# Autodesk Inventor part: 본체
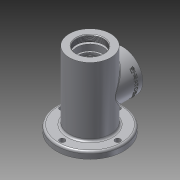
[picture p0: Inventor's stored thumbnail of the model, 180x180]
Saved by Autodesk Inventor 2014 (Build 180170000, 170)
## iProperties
Created: 2016-08
Part Number: 본체
Material: 알루미늄 6061
Document SubType Name: Modeling
Designer: 703-04
Density: 2.71 g/cm^3
Appearance: 알루미늄 - 평지
Mass: 729.842 g
Surface Area: 617.604 cm^2
Volume: 269.314 cm^3
Author: 703-04
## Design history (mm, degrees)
sketch "스케치1"
  geometry: C1 r 31 at (0, 0); 1 further point
  constraints: 1 centre point, 1 coincident
  dimensions: "d0" = 62 diameter of C1
extrude "돌출1" new body sketch "스케치1" stored distance "d1" = 102; taper "d2" = 0 deg
sketch "스케치2"
  geometry: C1 r 31 at (0, 0) reference; C2 r 50 at (0, 0)
  constraints: 1 centre point, 1 coincident
  dimensions: "d3" = 100 diameter of C2
extrude "돌출2" join sketch "스케치2" distance "d4" = 10; taper "d5" = 0 deg
sketch "스케치3"
  geometry: C1 r 50 at (0, 0) reference; C2 r 31 at (0, 0)
  constraints: 1 centre point, 1 coincident
  dimensions: "d6" = 62 diameter of C2
extrude "돌출3" join sketch "스케치3" distance "d7" = 3; taper "d8" = 0 deg
sketch "스케치4"
  geometry: L1 (31, 51)-(-31, 51) reference; L2 (0, 51)-(21, 51); L3 (21, 51)-(21, 42); L4 (21, 42)-(24, 42); L5 (24, 42)-(24, 39); L6 (24, 39)-(20, 39); L7 (20, 39)-(20, 30); L8 (20, 30)-(17.5, 30); L9 (17.5, 30)-(17.5, 26.75); L10 (17.5, 26.75)-(18.5, 26.75); L11 (18.5, 26.75)-(18.5, 25); L12 (18.5, 25)-(17.5, 25); L13 (17.5, 25)-(17.5, 14); L14 (17.5, 14)-(26, 14); L15 (26, 14)-(26, -24); L16 (26, -24)-(17.5, -24); L17 (17.5, -24)-(17.5, -35); L18 (17.5, -35)-(16.5, -35); L19 (16.5, -35)-(16.5, -40); L20 (16.5, -40)-(10, -40); L21 (10, -40)-(10, -42.7); L22 (10, -42.7)-(12.5, -42.7); L23 (12.5, -42.7)-(12.5, -49.3); L24 (12.5, -49.3)-(12.904, -50); L25 (12.904, -50)-(16.404, -50); L26 (16.404, -50)-(21, -64); L27 (-31, -64)-(31, -64) reference; L28 (21, -64)-(0, -64); L29 (0, -64)-(0, 42); L30 (21, 42)-(0, 42); L31 (0, 0)-(0, 42); L32 (0, 51)-(0, 60); 1 further point
  constraints: 60 end point, 13 parallel, 10 perpendicular, 3 point on line, 2 collinear, 2 midpoint, 2 vertical, 1 coincident
  dimensions: "d9" = 60 distance of L31.start L32.end; "d10" = 21 distance of L2.start L2.end; "d11" = 9 distance of L2.end L3.end; "d12" = 3 distance of L3.end L4.end; "d13" = 3 distance of L4.end L5.end; "d14" = 4 distance of L5.end L6.end; "d15" = 9 distance of L6.end L7.end; "d16" = 2.5 distance of L7.end L8.end; "d17" = 3.25 distance of L8.end L9.end; "d18" = 1 distance of L9.end L10.end; "d19" = 1.75 distance of L10.end L11.end; "d20" = 1 distance of L11.end L12.end; "d21" = 11 distance of L12.end L13.end; "d22" = 8.5 distance of L13.end L14.end; "d23" = 38 distance of L14.end L15.end; "d24" = 8.5 distance of L15.end L16.end; "d25" = 11 distance of L16.end L17.end; "d26" = 1 distance of L17.end L18.end; "d27" = 5 distance of L18.end L19.end; "d28" = 6.5 distance of L19.end L20.end; "d29" = 2.7 distance of L20.end L21.end; "d30" = 2.5 distance of L21.end L22.end; "d31" = 6.6 distance of L22.end L23.end; "d32" = 0.7 vertical distance of L23.end L24.end; "d33" = 30 deg angle of L23 L24; "d34" = 3.5 distance of L24.end L25.end; "d37" = 21 distance from line of L26.end L29
revolve "회전1" sketch "스케치4" stored, may be unused: angle "d36" = 90 deg
sketch "스케치5"
  geometry: C1 r 31 at (0, 0) reference; 1 further point
  constraints: 1 coincident
hole "구멍1" sketch "스케치5" at (0, 0) diameter "d38" = 40.376; stored, may be unused: countersink angle "d42" = 90 deg, drill point angle "d44" = 118 deg; dims "d39" = 9, "d40" = 4, "d41" = 2, "d43" = 9
chamfer "모따기1" distance "d45" = 1; stored, may be unused: second distance "d46" = 2, angle "d47" = 45 deg
fillet "모깎기1" dims "d48" = 0.3
fillet "모깎기2" dims "d49" = 3
node "작업 평면1"
sketch "스케치6"
  geometry: L1 (31, 51)-(-31, 51) reference; C1 r 30 at (0, -5); 1 further point
  constraints: 1 centre point
  dimensions: "d51" = 60 diameter of C1; "d52" = 56 distance from line of L1 C1.centre; "d53" = 0 horizontal distance of C1.centre point (0, 0)
extrude "돌출4" join sketch "스케치6" stored distance "d54" = 3; taper "d55" = 0 deg
sketch "스케치7" dims "d57" = 48
  geometry: L1 (0, 0)-(-24, 0); C1 r 30 at (0, 0) reference; C2 r 19 at (0, 0); 1 further point
  constraints: 2 coincident, 2 end point, 1 centre point, 1 horizontal, 1 horizontal alignment, 2 other
  dimensions: "d56" = 38 diameter of C2
extrude "돌출5" cut sketch "스케치7" stored distance "d58" = 3; taper "d59" = 0 deg
hole "구멍2" sketch "스케치7" diameter "d60" = 3.242; stored, may be unused: countersink angle "d64" = 90 deg, drill point angle "d66" = 118 deg; dims "d61" = 8, "d62" = 4, "d63" = 2, "d65" = 10
sketch "스케치8" dims "d70" = 83
  geometry: L1 (0, 0)-(0, 41.5); C1 r 50 at (0, 0) reference; 1 further point
  constraints: 2 coincident, 2 end point, 1 vertical, 1 vertical alignment, 2 other
hole "구멍3" sketch "스케치8" at (0, 41.5) diameter "d71" = 8; stored, may be unused: countersink angle "d75" = 90 deg, drill point angle "d77" = 118 deg; dims "d72" = 8, "d73" = 4, "d74" = 2, "d76" = 10
node "작업 평면2"
sketch "스케치9"
  geometry: L1 (31, 51)-(-31, 51) reference; L2 (49, 25)-(49, -35) reference; 2 further points
  constraints: 1 other
  dimensions: "d82" = 10 distance from line of L2 point (39, -5); "d83" = 56 distance from line of L1 point (39, -5)
feature "엠보싱1" sketch "스케치9" dims "d11" = 9, "d84" = 0.5, "d85" = 0
chamfer "모따기2" distance "d86" = 1; stored, may be unused: second distance "d87" = 2, angle "d88" = 45 deg
fillet "모깎기3" dims "d89" = 3
node "작업 평면3"
sketch "스케치10"
  geometry: C1 r 19 at (0, 0) reference; 1 further point
extrude "돌출6" cut sketch "스케치10" distance "d91" = 15; taper "d92" = 0 deg
node "솔리드1"
pattern_circular "원형 패턴1" dims angle "d68" = 360 deg
pattern_circular "원형 패턴2" dims angle "d79" = 360 deg
other parameters: "d35" = 42, "d50" = 49, "d90" = -17.25
